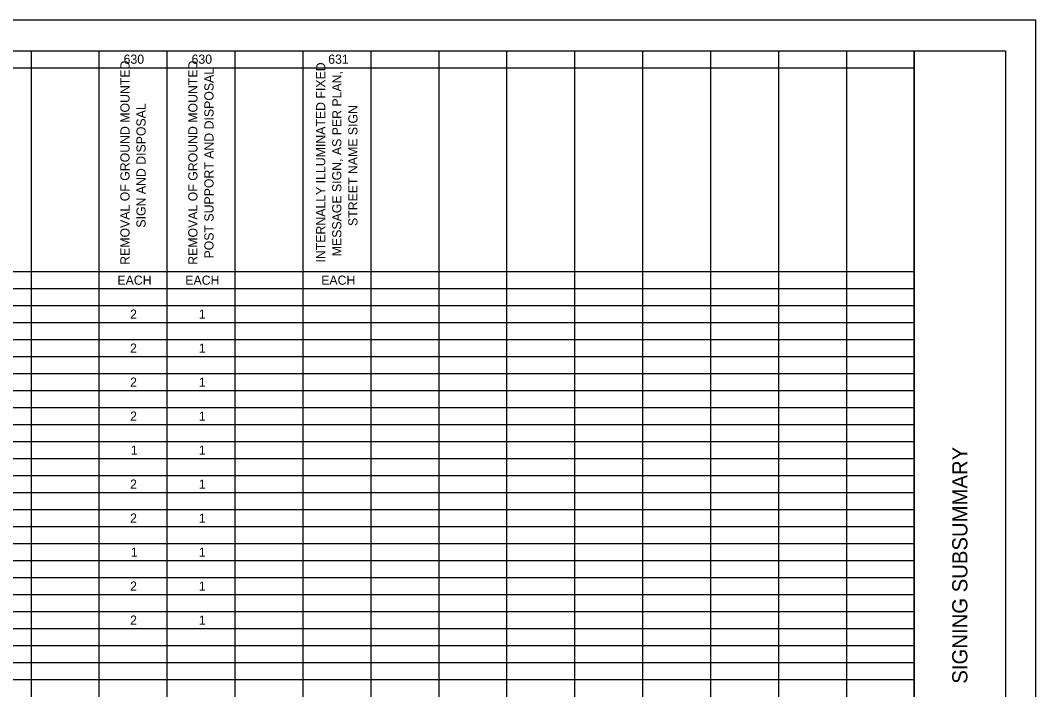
# Model space of a CAD drawing. Extents: x 0 to 34, y 0 to 22.
# Drawn here: x 17.27 to 34, y 10.97 to 22 of the extents above; entities that cross this region are included whole.
import ezdxf

# ---------------------------------------------------------------- set-up
doc = ezdxf.new("R2010")
doc.units = 0
for name, color, linetype in [('SH_Border', 7, 'Continuous'), ('SH_Cut_Line', 7, 'Continuous'), ('SH_Data', 7, 'Continuous'), ('SH_Text', 7, 'Continuous')]:
    doc.layers.add(name, color=color, linetype=linetype)

msp = doc.modelspace()

# ---------------------------------------------------------------- linework, layer by layer
at = {"layer": 'SH_Border'}
msp.add_line((32, 0.5), (32, 21.5), dxfattribs=at)
msp.add_lwpolyline([(1.5, 21.5), (33.5, 21.5), (33.5, 0.5), (1.5, 0.5)], close=True, dxfattribs=at)
at = {"layer": 'SH_Cut_Line'}
msp.add_lwpolyline([(0, 0), (34, 0), (34, 22), (0, 22)], close=True, dxfattribs=at)
at = {"layer": 'SH_Text'}
for p, q in [((1.5, 21.5), (32, 21.5)), ((17.45, 21.5), (17.45, 0.5)), ((18.569, 21.5), (18.569, 0.5)), ((19.688, 21.5), (19.688, 0.5)), ((20.807, 21.5), (20.807, 0.5)), ((21.927, 21.5), (21.927, 0.5)), ((23.046, 21.5), (23.046, 0.5)), ((24.165, 21.5), (24.165, 0.5)), ((25.284, 21.5), (25.284, 0.5)), ((26.404, 21.5), (26.404, 0.5)), ((27.523, 21.5), (27.523, 0.5)), ((28.642, 21.5), (28.642, 0.5)), ((29.761, 21.5), (29.761, 0.5)), ((30.881, 21.5), (30.881, 0.5)), ((32, 21.5), (32, 0.5)), ((10.734, 21.22), (32, 21.22)), ((10.734, 17.86), (32, 17.86)), ((1.5, 17.58), (32, 17.58)), ((1.5, 17.3), (32, 17.3)), ((1.5, 17.02), (32, 17.02)), ((1.5, 16.74), (32, 16.74)), ((1.5, 16.46), (32, 16.46)), ((1.5, 16.18), (32, 16.18)), ((1.5, 15.9), (32, 15.9)), ((1.5, 15.62), (32, 15.62)), ((1.5, 15.34), (32, 15.34)), ((1.5, 15.06), (32, 15.06)), ((1.5, 14.78), (32, 14.78)), ((1.5, 14.5), (32, 14.5)), ((1.5, 14.22), (32, 14.22)), ((1.5, 13.94), (32, 13.94)), ((1.5, 13.66), (32, 13.66)), ((1.5, 13.38), (32, 13.38)), ((1.5, 13.1), (32, 13.1)), ((1.5, 12.82), (32, 12.82)), ((1.5, 12.54), (32, 12.54)), ((1.5, 12.26), (32, 12.26)), ((1.5, 11.98), (32, 11.98)), ((1.5, 11.7), (32, 11.7)), ((1.5, 11.42), (32, 11.42)), ((1.5, 11.14), (32, 11.14))]:
    msp.add_line(p, q, dxfattribs=at)

# ---------------------------------------------------------------- texts
at = {"layer": 'SH_Data'}
msp.add_text('SIGNING SUBSUMMARY', height=0.25, rotation=90, dxfattribs=at).set_placement((32.875, 11.074))
at = {"layer": 'SH_Text'}
for s, height, p in [('630', 0.1515, (18.974, 21.284)), ('630', 0.1515, (20.094, 21.284)), ('631', 0.1515, (22.345, 21.284)), ('EACH', 0.1515, (18.872, 17.644)), ('EACH', 0.1515, (19.991, 17.644)), ('EACH', 0.1515, (22.229, 17.644)), ('2', 0.152, (19.081, 17.084)), ('1', 0.152, (20.212, 17.084)), ('2', 0.152, (19.081, 16.524)), ('1', 0.152, (20.212, 16.524)), ('2', 0.152, (19.081, 15.964)), ('1', 0.152, (20.212, 15.964)), ('2', 0.152, (19.081, 15.404)), ('1', 0.152, (20.212, 15.404)), ('1', 0.152, (19.093, 14.844)), ('1', 0.152, (20.212, 14.844)), ('2', 0.152, (19.081, 14.284)), ('1', 0.152, (20.212, 14.284)), ('2', 0.152, (19.081, 13.724)), ('1', 0.152, (20.212, 13.724)), ('1', 0.152, (19.093, 13.164)), ('1', 0.152, (20.212, 13.164)), ('2', 0.152, (19.081, 12.604)), ('1', 0.152, (20.212, 12.604)), ('2', 0.152, (19.081, 12.044)), ('1', 0.152, (20.212, 12.044))]:
    msp.add_text(s, height=height, dxfattribs=at).set_placement(p)
for s, p in [('REMOVAL OF GROUND MOUNTED ', (19.072, 17.973)), ('REMOVAL OF GROUND MOUNTED ', (20.191, 17.973)), ('INTERNALLY ILLUMINATED FIXED ', (22.297, 18.01)), ('POST SUPPORT AND DISPOSAL', (20.456, 18.077)), ('MESSAGE SIGN, AS PER PLAN, ', (22.562, 18.114)), ('SIGN AND DISPOSAL', (19.337, 18.585)), ('STREET NAME SIGN', (22.827, 18.612))]:
    msp.add_text(s, height=0.15143, rotation=90, dxfattribs=at).set_placement(p)

doc.saveas('drawing.dxf')
